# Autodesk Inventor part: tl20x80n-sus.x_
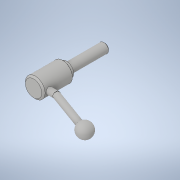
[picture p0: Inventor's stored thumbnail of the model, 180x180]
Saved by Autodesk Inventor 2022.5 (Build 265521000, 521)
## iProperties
Created: 2021-02
Part Number: tl20x80n-sus.x_
Material: 一般
Document SubType Name: Modeling
Designer: ImaoCorp
Density: 1 g/cm^3
Appearance: 既定
Sending System: SOLIDWORKS 2019-2019304
MC: AMD64
MC_MODEL: Intel64 Family 6 Model 60 Stepping 3, GenuineIntel
OS: Windows_NT
FRU: Parasolid Version 31.0, build 290,  9- 1-2019
FORMAT: text
GUISE: transmit
KEY: tl20x80n-sus
FILE: tl20x80n-sus.x_t
DATE: Mon Feb 22 14:51:58 2021
Author: ImaoCorp
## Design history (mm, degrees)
feature "Base1"
node "ソリッド1"
